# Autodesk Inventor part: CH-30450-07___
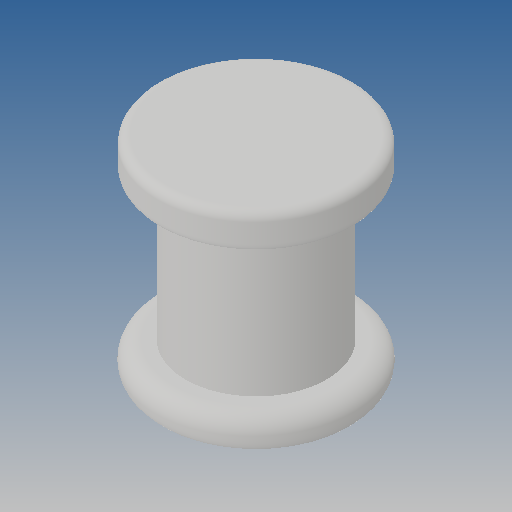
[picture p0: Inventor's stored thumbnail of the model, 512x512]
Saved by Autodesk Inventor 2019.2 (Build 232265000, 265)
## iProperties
Created: 2010-06
Part Number: CH-30450-07___
Material: Ogólny
Document SubType Name: Modeling
Designer: CADENGINEERING4
Density: 1 g/cm^3
Appearance: Domyślna
Author: CADENGINEERING4
Revision Number: ANY
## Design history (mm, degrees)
feature "NONE"
node "Bryła1"
